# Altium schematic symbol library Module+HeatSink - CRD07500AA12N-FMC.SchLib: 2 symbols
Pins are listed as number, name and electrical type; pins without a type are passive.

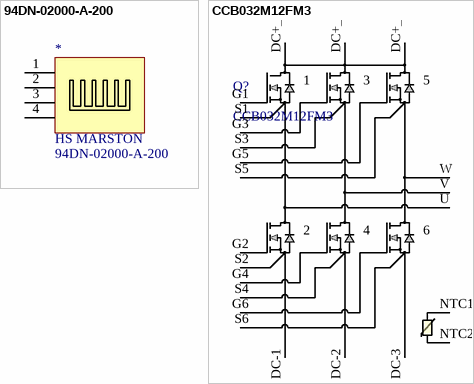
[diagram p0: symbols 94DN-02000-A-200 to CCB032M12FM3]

## 94DN-02000-A-200
designator *  Manufacturer: HS MARSTON  (hidden comment: 94DN-02000-A-200)
Heat Sink, Extruded Range - 4, Black Anodized, 0.7 C/w, 40 Mm, 123 Mm, 200 Mm Rohs Compliant: Yes; Natural Thermal Resistance: 0.7°C/W
footprint 94DN-02000-A-200
pins: 1, 2, 3, 4

## CCB032M12FM3
designator Q?
No Description Available; Mfr_Name: Cree Wolfspeed; Type: DEV
footprint FM3_SIX-PACK_3PHASE_CRW
pins: DC+_1, DC+_2, DC+_3, DC-1, DC-2, DC-3, G1, G2, G3, G4, G5, G6, NTC1, NTC2, S1, S2, S3, S4, S5, S6, U, V, W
